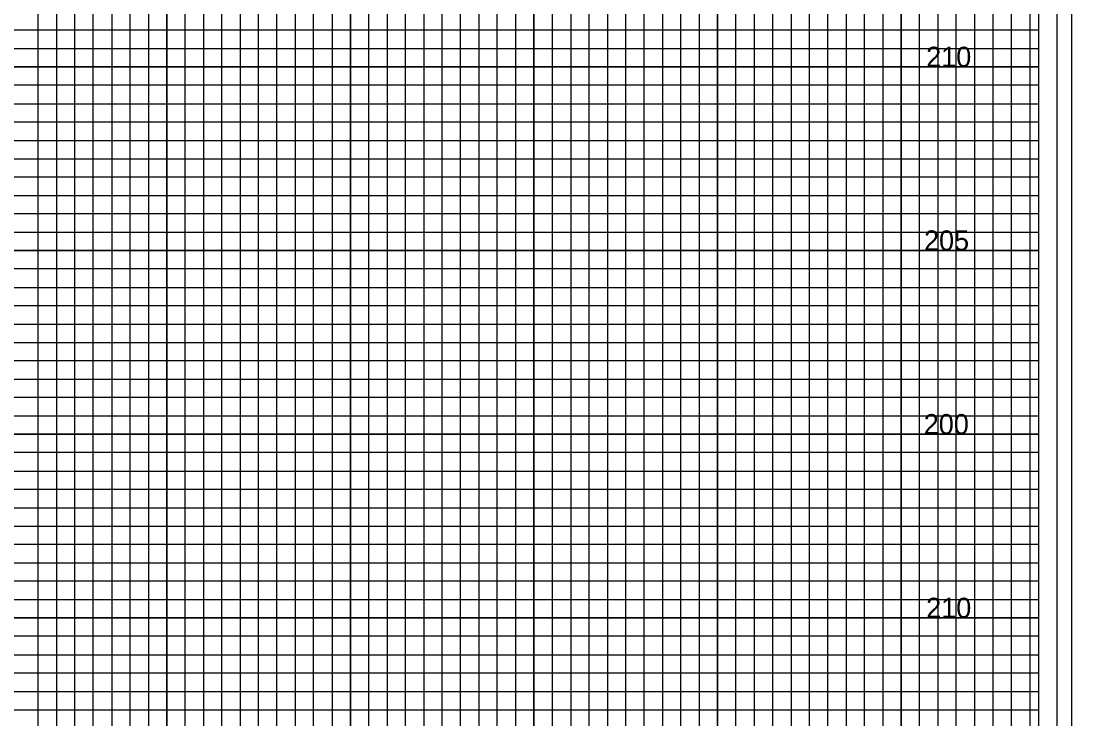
# Model space of a CAD drawing. Extents: x -4 to 103, y -2 to 138.
# Drawn here: x 74.78 to 103.4, y 32.25 to 51.25 of the extents above; entities that cross this region are included whole.
import ezdxf

# ---------------------------------------------------------------- set-up
doc = ezdxf.new("R2010")
doc.units = 0
for name, color, linetype in [('Exist XS Ground Line', 7, 'Continuous'), ('Old_Level_10', 7, 'Continuous'), ('Old_Level_5', 7, 'Continuous'), ('Old_Level_8', 7, 'Continuous'), ('Prop XS Dump Level', 7, 'Continuous'), ('Prop XS Elevation Labels', 7, 'Continuous'), ('Prop XS Finish Grade', 7, 'Continuous')]:
    doc.layers.add(name, color=color, linetype=linetype)

msp = doc.modelspace()

# ---------------------------------------------------------------- linework, layer by layer
at = {"layer": 'Exist XS Ground Line'}
msp.add_lwpolyline([(103, 66), (-2.8, 66), (-2.8, -1), (103, -1)], close=True, dxfattribs=at)
at = {"layer": 'Old_Level_10'}
for p, q in [((91.25, 0), (91.25, 63.425)), ((93.75, 0), (93.75, 63.425)), ((96.25, 0), (96.25, 63.425)), ((98.75, 0), (98.75, 63.425)), ((101.25, 0), (101.25, 63.425)), ((76.25, 0), (76.25, 62)), ((78.75, 0), (78.75, 62)), ((81.25, 0), (81.25, 62)), ((83.75, 0), (83.75, 62)), ((86.25, 0), (86.25, 62)), ((88.75, 0), (88.75, 62)), ((0, 50), (102.5, 50)), ((0, 47.5), (102.5, 47.5)), ((0, 45), (102.5, 45)), ((0, 42.5), (102.5, 42.5)), ((0, 40), (102.5, 40)), ((0, 37.5), (102.5, 37.5)), ((0, 35), (102.5, 35)), ((0, 32.5), (102.5, 32.5))]:
    msp.add_line(p, q, dxfattribs=at)
at = {"layer": 'Old_Level_5'}
msp.add_lwpolyline([(103.4, 67.4), (-3.5, 67.4), (-3.5, -2.425), (103.4, -2.425)], close=True, dxfattribs=at)
at = {"layer": 'Old_Level_8'}
for points in [[(91.25, 0), (91.25, 63.425), (93.75, 63.425), (93.75, 0)], [(96.25, 0), (96.25, 63.425), (98.75, 63.425), (98.75, 0)], [(101.25, 0), (101.25, 63.425)], [(76.25, 0), (76.25, 62), (78.75, 62), (78.75, 0)], [(81.25, 0), (81.25, 62), (83.75, 62), (83.75, 0)], [(86.25, 0), (86.25, 62), (88.75, 62), (88.75, 0)], [(0, 47.5), (102.5, 47.5), (102.5, 50), (0, 50)], [(0, 42.5), (102.5, 42.5), (102.5, 45), (0, 45)], [(0, 37.5), (102.5, 37.5), (102.5, 40), (0, 40)], [(0, 32.5), (102.5, 32.5), (102.5, 35), (0, 35)]]:
    msp.add_lwpolyline(points, dxfattribs=at)
at = {"layer": 'Prop XS Elevation Labels'}
msp.add_lwpolyline([(102.5, 65), (0, 65), (0, 0), (102.5, 0)], close=True, dxfattribs=at)
at = {"layer": 'Prop XS Finish Grade'}
for points in [[(90.25, 0), (90.25, 63.425), (90.75, 63.425), (90.75, 0)], [(91.75, 0), (91.75, 63.425), (92.25, 63.425), (92.25, 0)], [(92.75, 0), (92.75, 63.425), (93.25, 63.425), (93.25, 0)], [(94.25, 0), (94.25, 63.425), (94.75, 63.425), (94.75, 0)], [(95.25, 0), (95.25, 63.425), (95.75, 63.425), (95.75, 0)], [(96.75, 0), (96.75, 63.425), (97.25, 63.425), (97.25, 0)], [(97.75, 0), (97.75, 63.425), (98.25, 63.425), (98.25, 0)], [(99.25, 0), (99.25, 63.425), (99.75, 63.425), (99.75, 0)], [(100.25, 0), (100.25, 63.425)], [(100.25, 63.425), (100.75, 63.425), (100.75, 0), (101.75, 0), (101.75, 63.425), (102.25, 63.425), (102.25, 0)], [(75.25, 0), (75.25, 62), (75.75, 62), (75.75, 0)], [(76.75, 0), (76.75, 62), (77.25, 62), (77.25, 0)], [(77.75, 0), (77.75, 62), (78.25, 62), (78.25, 0)], [(79.25, 0), (79.25, 62), (79.75, 62), (79.75, 0)], [(80.25, 0), (80.25, 62), (80.75, 62), (80.75, 0)], [(81.75, 0), (81.75, 62), (82.25, 62), (82.25, 0)], [(82.75, 0), (82.75, 62), (83.25, 62), (83.25, 0)], [(84.25, 0), (84.25, 62), (84.75, 62), (84.75, 0)], [(85.25, 0), (85.25, 62), (85.75, 62), (85.75, 0)], [(86.75, 0), (86.75, 62), (87.25, 62), (87.25, 0)], [(87.75, 0), (87.75, 62), (88.25, 62), (88.25, 0)], [(89.25, 0), (89.25, 62), (89.75, 62), (89.75, 0)], [(0, 50.5), (102.5, 50.5), (102.5, 51), (0, 51)], [(0, 49), (102.5, 49), (102.5, 49.5), (0, 49.5)], [(0, 48), (102.5, 48), (102.5, 48.5), (0, 48.5)], [(0, 46.5), (102.5, 46.5), (102.5, 47), (0, 47)], [(0, 45.5), (102.5, 45.5), (102.5, 46), (0, 46)], [(0, 44), (102.5, 44), (102.5, 44.5), (0, 44.5)], [(0, 43), (102.5, 43), (102.5, 43.5), (0, 43.5)], [(0, 41.5), (102.5, 41.5), (102.5, 42), (0, 42)], [(0, 40.5), (102.5, 40.5), (102.5, 41), (0, 41)], [(0, 39), (102.5, 39), (102.5, 39.5), (0, 39.5)], [(0, 38), (102.5, 38), (102.5, 38.5), (0, 38.5)], [(0, 36.5), (102.5, 36.5), (102.5, 37), (0, 37)], [(0, 35.5), (102.5, 35.5), (102.5, 36), (0, 36)], [(0, 34), (102.5, 34), (102.5, 34.5), (0, 34.5)], [(0, 33), (102.5, 33), (102.5, 33.5), (0, 33.5)]]:
    msp.add_lwpolyline(points, dxfattribs=at)

# ---------------------------------------------------------------- texts
at = {"layer": 'Prop XS Dump Level'}
for s, p in [('210', (99.43, 50)), ('205', (99.372, 45)), ('200', (99.364, 40)), ('210', (99.43, 35))]:
    msp.add_text(s, height=0.55, dxfattribs=at).set_placement(p)

doc.saveas('drawing.dxf')
